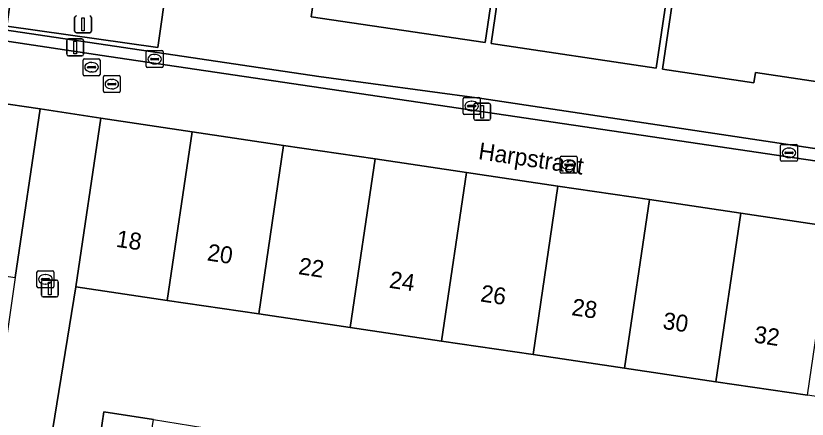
# Model space of a CAD drawing. Extents: x 164148 to 165261, y 382513 to 383432.
# Drawn here: x 164428.5 to 164475.24, y 383341.98 to 383365.77 of the extents above; entities that cross this region are included whole.
import ezdxf

# ---------------------------------------------------------------- set-up
doc = ezdxf.new("R2010")
doc.units = 0
for name, color, linetype in [('IMGEO_Brandkraan', 7, 'Continuous'), ('IMGEO_Erf', 7, 'Continuous'), ('IMGEO_Groenvoorziening', 7, 'Continuous'), ('IMGEO_Hek', 7, 'Continuous'), ('IMGEO_Kolk', 7, 'Continuous'), ('IMGEO_Lichtmast', 7, 'Continuous'), ('IMGEO_Openbare_ruimte_label', 7, 'Continuous'), ('IMGEO_Pand', 7, 'Continuous'), ('IMGEO_Pand_nummerreeks', 7, 'Continuous'), ('IMGEO_Rioolput', 7, 'Continuous'), ('IMGEO_Voetpad_open', 7, 'Continuous')]:
    doc.layers.add(name, color=color, linetype=linetype)

msp = doc.modelspace()

# ---------------------------------------------------------------- linework, layer by layer
at = {"layer": 'IMGEO_Brandkraan'}
for p, q in [((164460.657, 383356.558), (164460.657, 383357.41)), ((164460.732, 383357.484), (164461.584, 383357.484)), ((164461.658, 383357.41), (164461.658, 383356.558)), ((164460.916, 383356.978), (164460.916, 383356.99)), ((164461.354, 383356.941), (164460.956, 383356.941)), ((164460.959, 383357.027), (164461.357, 383357.027)), ((164461.145, 383357.264), (164461.17, 383357.264)), ((164461.4, 383356.99), (164461.4, 383356.978)), ((164461.584, 383356.484), (164460.732, 383356.484)), ((164461.168, 383356.704), (164461.143, 383356.704))]:
    msp.add_line(p, q, dxfattribs=at)
for points in [[(164460.657, 383356.558), (164460.657, 383357.41)], [(164460.732, 383357.484), (164461.584, 383357.484)], [(164461.658, 383357.41), (164461.658, 383356.558)], [(164461.584, 383356.484), (164460.732, 383356.484)]]:
    msp.add_lwpolyline(points, dxfattribs=at)
for centre, radius, start, end in [((164460.734, 383357.408), 0.0765, 91.552, 178.448), ((164460.734, 383357.408), 0.0765, 91.552, 178.448), ((164461.582, 383357.408), 0.0765, 1.552, 88.448), ((164461.582, 383357.408), 0.0765, 1.552, 88.448), ((164460.956, 383356.987), 0.0403, 85.8775, 175.7526), ((164460.953, 383356.977), 0.0366, 178.938, 274.7102), ((164461.357, 383356.984), 0.043, 264.8664, 352.4533), ((164461.361, 383356.989), 0.0386, 1.7309, 96.639), ((164460.734, 383356.56), 0.0765, 181.552, 268.448), ((164460.734, 383356.56), 0.0765, 181.552, 268.448), ((164461.582, 383356.56), 0.0765, 271.552, 358.448), ((164461.582, 383356.56), 0.0765, 271.552, 358.448)]:
    msp.add_arc(centre, radius, start, end, dxfattribs=at)
for centre, major_axis, ratio, start_param, end_param in [((164461.144, 383356.984), (-0.387, 0.002), 0.722429, 4.712389, 7.853982), ((164461.169, 383356.984), (-0.39, 0.002), 0.717154, 1.570796, 4.712389)]:
    msp.add_ellipse(centre, major_axis=major_axis, ratio=ratio, start_param=start_param, end_param=end_param, dxfattribs=at)
at = {"layer": 'IMGEO_Erf'}
for points in [[(164496.172, 383394.152), (164495.205, 383395.312), (164485.846, 383406.541), (164475.669, 383398.705), (164457.962, 383391.157), (164451.983, 383388.33), (164443.993, 383384.279), (164439.097, 383382.204), (164431.513, 383378.99), (164421.044, 383374.785), (164425.292, 383365.326), (164446.405, 383362.194), (164456.026, 383360.895), (164526.656, 383350.3), (164530.567, 383353.579)], [(164444.272, 383366.824), (164437.44, 383367.793), (164436.888, 383363.902), (164427.967, 383365.167), (164429.354, 383374.939), (164445.106, 383372.705)], [(164466.322, 383362.688), (164456.569, 383364.138), (164457.451, 383370.073), (164467.204, 383368.623)], [(164480.652, 383342.588), (164475.251, 383343.388), (164469.85, 383344.188), (164464.449, 383344.988), (164459.047, 383345.788), (164453.646, 383346.588), (164448.245, 383347.387), (164442.844, 383348.187), (164437.443, 383348.987), (164432.042, 383349.787), (164430.539, 383340.579), (164484.639, 383332.608), (164486.005, 383341.796)], [(164436.622, 383341.954), (164439.537, 383341.498), (164439.224, 383339.495), (164436.308, 383339.951), (164433.393, 383340.407), (164433.706, 383342.41)]]:
    msp.add_lwpolyline(points, close=True, dxfattribs=at)
for points in [[(164457.191, 383370.718), (164456.22, 383364.19), (164445.943, 383365.718), (164446.895, 383372.431)], [(164511.684, 383370.001), (164510.233, 383359.776), (164501.382, 383361.033), (164501.681, 383363.14), (164500, 383363.392), (164499.006, 383363.541), (164498.259, 383358.532), (164472.187, 383362.422), (164472.098, 383361.829), (164466.687, 383362.633), (164467.658, 383369.162)]]:
    msp.add_lwpolyline(points, dxfattribs=at)
at = {"layer": 'IMGEO_Groenvoorziening'}
msp.add_lwpolyline([(164433.986, 383363.368), (164526.587, 383349.71), (164526.656, 383350.3), (164456.026, 383360.895), (164446.405, 383362.194), (164425.292, 383365.326), (164425.46, 383364.655)], close=True, dxfattribs=at)
at = {"layer": 'IMGEO_Hek'}
msp.add_lwpolyline([(164526.656, 383350.3), (164456.026, 383360.895), (164446.405, 383362.194), (164425.292, 383365.326)], dxfattribs=at)
at = {"layer": 'IMGEO_Kolk'}
for p, q in [((164436.202, 383362.793), (164436.202, 383363.645)), ((164436.277, 383363.719), (164437.129, 383363.719)), ((164436.69, 383363.499), (164436.715, 383363.499)), ((164437.203, 383363.645), (164437.203, 383362.793)), ((164436.461, 383363.213), (164436.461, 383363.225)), ((164436.899, 383363.176), (164436.501, 383363.176)), ((164436.504, 383363.262), (164436.902, 383363.262)), ((164436.945, 383363.225), (164436.945, 383363.213)), ((164437.129, 383362.719), (164436.277, 383362.719)), ((164436.713, 383362.939), (164436.688, 383362.939)), ((164454.921, 383360.025), (164454.921, 383360.877)), ((164454.996, 383360.951), (164455.848, 383360.951)), ((164455.409, 383360.731), (164455.434, 383360.731)), ((164455.922, 383360.877), (164455.922, 383360.025)), ((164455.18, 383360.445), (164455.18, 383360.457)), ((164455.618, 383360.408), (164455.22, 383360.408)), ((164455.223, 383360.494), (164455.621, 383360.494)), ((164455.664, 383360.457), (164455.664, 383360.445)), ((164455.848, 383359.951), (164454.996, 383359.951)), ((164455.432, 383360.171), (164455.407, 383360.171)), ((164473.664, 383357.264), (164473.664, 383358.116)), ((164473.739, 383358.19), (164474.591, 383358.19)), ((164474.152, 383357.97), (164474.177, 383357.97)), ((164474.665, 383358.116), (164474.665, 383357.264)), ((164473.923, 383357.684), (164473.923, 383357.696)), ((164474.361, 383357.647), (164473.963, 383357.647)), ((164473.966, 383357.733), (164474.364, 383357.733)), ((164474.175, 383357.41), (164474.15, 383357.41)), ((164474.407, 383357.696), (164474.407, 383357.684)), ((164474.591, 383357.19), (164473.739, 383357.19)), ((164429.748, 383349.803), (164429.748, 383350.655)), ((164429.823, 383350.729), (164430.675, 383350.729)), ((164430.236, 383350.509), (164430.261, 383350.509)), ((164430.749, 383350.655), (164430.749, 383349.803)), ((164430.007, 383350.223), (164430.007, 383350.235)), ((164430.445, 383350.186), (164430.047, 383350.186)), ((164430.05, 383350.272), (164430.448, 383350.272)), ((164430.259, 383349.949), (164430.234, 383349.949)), ((164430.491, 383350.235), (164430.491, 383350.223)), ((164430.675, 383349.729), (164429.823, 383349.729))]:
    msp.add_line(p, q, dxfattribs=at)
for points in [[(164436.202, 383362.793), (164436.202, 383363.645)], [(164436.277, 383363.719), (164437.129, 383363.719)], [(164437.203, 383363.645), (164437.203, 383362.793)], [(164437.129, 383362.719), (164436.277, 383362.719)], [(164454.921, 383360.025), (164454.921, 383360.877)], [(164454.996, 383360.951), (164455.848, 383360.951)], [(164455.922, 383360.877), (164455.922, 383360.025)], [(164455.848, 383359.951), (164454.996, 383359.951)], [(164473.664, 383357.264), (164473.664, 383358.116)], [(164473.739, 383358.19), (164474.591, 383358.19)], [(164474.665, 383358.116), (164474.665, 383357.264)], [(164474.591, 383357.19), (164473.739, 383357.19)], [(164429.748, 383349.803), (164429.748, 383350.655)], [(164429.823, 383350.729), (164430.675, 383350.729)], [(164430.749, 383350.655), (164430.749, 383349.803)], [(164430.675, 383349.729), (164429.823, 383349.729)]]:
    msp.add_lwpolyline(points, dxfattribs=at)
for centre, radius, start, end in [((164436.279, 383363.643), 0.0765, 91.552, 178.448), ((164436.279, 383363.643), 0.0765, 91.552, 178.448), ((164437.127, 383363.643), 0.0765, 1.552, 88.448), ((164437.127, 383363.643), 0.0765, 1.552, 88.448), ((164436.501, 383363.222), 0.0403, 85.8775, 175.7526), ((164436.498, 383363.212), 0.0366, 178.938, 274.7102), ((164436.902, 383363.219), 0.043, 264.8664, 352.4533), ((164436.906, 383363.224), 0.0386, 1.7309, 96.639), ((164436.279, 383362.795), 0.0765, 181.552, 268.448), ((164436.279, 383362.795), 0.0765, 181.552, 268.448), ((164437.127, 383362.795), 0.0765, 271.552, 358.448), ((164437.127, 383362.795), 0.0765, 271.552, 358.448), ((164454.998, 383360.875), 0.0765, 91.552, 178.448), ((164454.998, 383360.875), 0.0765, 91.552, 178.448), ((164455.846, 383360.875), 0.0765, 1.552, 88.448), ((164455.846, 383360.875), 0.0765, 1.552, 88.448), ((164455.22, 383360.454), 0.0403, 85.8775, 175.7526), ((164455.217, 383360.444), 0.0366, 178.938, 274.7102), ((164455.621, 383360.451), 0.043, 264.8664, 352.4533), ((164455.625, 383360.456), 0.0386, 1.7309, 96.639), ((164454.998, 383360.027), 0.0765, 181.552, 268.448), ((164454.998, 383360.027), 0.0765, 181.552, 268.448), ((164455.846, 383360.027), 0.0765, 271.552, 358.448), ((164455.846, 383360.027), 0.0765, 271.552, 358.448), ((164473.741, 383358.114), 0.0765, 91.552, 178.448), ((164473.741, 383358.114), 0.0765, 91.552, 178.448), ((164474.589, 383358.114), 0.0765, 1.552, 88.448), ((164474.589, 383358.114), 0.0765, 1.552, 88.448), ((164473.963, 383357.693), 0.0403, 85.8775, 175.7526), ((164473.96, 383357.683), 0.0366, 178.938, 274.7102), ((164474.364, 383357.69), 0.043, 264.8664, 352.4533), ((164474.368, 383357.695), 0.0386, 1.7309, 96.639), ((164473.741, 383357.266), 0.0765, 181.552, 268.448), ((164473.741, 383357.266), 0.0765, 181.552, 268.448), ((164474.589, 383357.266), 0.0765, 271.552, 358.448), ((164474.589, 383357.266), 0.0765, 271.552, 358.448), ((164429.825, 383350.653), 0.0765, 91.552, 178.448), ((164429.825, 383350.653), 0.0765, 91.552, 178.448), ((164430.673, 383350.653), 0.0765, 1.552, 88.448), ((164430.673, 383350.653), 0.0765, 1.552, 88.448), ((164430.047, 383350.232), 0.0403, 85.8775, 175.7526), ((164430.044, 383350.222), 0.0366, 178.938, 274.7102), ((164430.448, 383350.229), 0.043, 264.8664, 352.4533), ((164430.452, 383350.234), 0.0386, 1.7309, 96.639), ((164429.825, 383349.805), 0.0765, 181.552, 268.448), ((164429.825, 383349.805), 0.0765, 181.552, 268.448), ((164430.673, 383349.805), 0.0765, 271.552, 358.448), ((164430.673, 383349.805), 0.0765, 271.552, 358.448)]:
    msp.add_arc(centre, radius, start, end, dxfattribs=at)
for centre, major_axis, ratio, start_param, end_param in [((164436.689, 383363.219), (-0.387, 0.002), 0.722429, 4.712389, 7.853982), ((164436.714, 383363.219), (-0.39, 0.002), 0.717154, 1.570796, 4.712389), ((164455.408, 383360.451), (-0.387, 0.002), 0.722429, 4.712389, 7.853982), ((164455.433, 383360.451), (-0.39, 0.002), 0.717154, 1.570796, 4.712389), ((164474.151, 383357.69), (-0.387, 0.002), 0.722429, 4.712389, 7.853982), ((164474.176, 383357.69), (-0.39, 0.002), 0.717154, 1.570796, 4.712389), ((164430.235, 383350.229), (-0.387, 0.002), 0.722429, 4.712389, 7.853982), ((164430.26, 383350.229), (-0.39, 0.002), 0.717154, 1.570796, 4.712389)]:
    msp.add_ellipse(centre, major_axis=major_axis, ratio=ratio, start_param=start_param, end_param=end_param, dxfattribs=at)
at = {"layer": 'IMGEO_Lichtmast'}
for p, q in [((164431.975, 383364.871), (164431.975, 383365.671)), ((164431.975, 383365.671), (164431.975, 383364.871)), ((164432.965, 383365.671), (164432.965, 383364.871)), ((164432.965, 383364.871), (164432.965, 383365.671)), ((164431.608, 383364.411), (164432.398, 383364.411)), ((164432.398, 383364.411), (164431.608, 383364.411)), ((164432.865, 383364.771), (164432.075, 383364.771)), ((164432.075, 383364.771), (164432.865, 383364.771)), ((164431.508, 383363.511), (164431.508, 383364.311)), ((164431.508, 383364.311), (164431.508, 383363.511)), ((164432.498, 383364.311), (164432.498, 383363.511)), ((164432.498, 383363.511), (164432.498, 383364.311)), ((164432.398, 383363.411), (164431.608, 383363.411)), ((164431.608, 383363.411), (164432.398, 383363.411)), ((164455.551, 383359.715), (164455.551, 383360.515)), ((164455.551, 383360.515), (164455.551, 383359.715)), ((164455.651, 383360.615), (164456.441, 383360.615)), ((164456.441, 383360.615), (164455.651, 383360.615)), ((164456.541, 383360.515), (164456.541, 383359.715)), ((164456.541, 383359.715), (164456.541, 383360.515)), ((164456.441, 383359.615), (164455.651, 383359.615)), ((164455.651, 383359.615), (164456.441, 383359.615)), ((164430.013, 383349.287), (164430.013, 383350.087)), ((164430.013, 383350.087), (164430.013, 383349.287)), ((164430.113, 383350.187), (164430.903, 383350.187)), ((164430.903, 383350.187), (164430.113, 383350.187)), ((164431.003, 383350.087), (164431.003, 383349.287)), ((164431.003, 383349.287), (164431.003, 383350.087)), ((164430.903, 383349.187), (164430.113, 383349.187)), ((164430.113, 383349.187), (164430.903, 383349.187))]:
    msp.add_line(p, q, dxfattribs=at)
for points in [[(164432.395, 383365.646), (164432.545, 383365.646), (164432.545, 383364.896), (164432.395, 383364.896), (164432.395, 383365.646)], [(164431.928, 383364.286), (164432.078, 383364.286), (164432.078, 383363.536), (164431.928, 383363.536), (164431.928, 383364.286)], [(164455.971, 383360.49), (164456.121, 383360.49), (164456.121, 383359.74), (164455.971, 383359.74), (164455.971, 383360.49)], [(164430.433, 383350.062), (164430.583, 383350.062), (164430.583, 383349.312), (164430.433, 383349.312), (164430.433, 383350.062)]]:
    msp.add_lwpolyline(points, dxfattribs=at)
for centre, start, end in [((164432.075, 383365.671), 90, 180), ((164432.075, 383365.671), 90, 180), ((164432.865, 383365.671), 0, 90), ((164432.865, 383365.671), 360, 90), ((164432.075, 383364.871), 180, 270), ((164432.075, 383364.871), 180, 270), ((164432.865, 383364.871), 270, 0), ((164432.865, 383364.871), 270, 0), ((164431.608, 383364.311), 90, 180), ((164431.608, 383364.311), 90, 180), ((164432.398, 383364.311), 0, 90), ((164432.398, 383364.311), 360, 90), ((164431.608, 383363.511), 180, 270), ((164431.608, 383363.511), 180, 270), ((164432.398, 383363.511), 270, 0), ((164432.398, 383363.511), 270, 0), ((164455.651, 383360.515), 90, 180), ((164455.651, 383360.515), 90, 180), ((164456.441, 383360.515), 0, 90), ((164456.441, 383360.515), 360, 90), ((164455.651, 383359.715), 180, 270), ((164455.651, 383359.715), 180, 270), ((164456.441, 383359.715), 270, 0), ((164456.441, 383359.715), 270, 0), ((164430.113, 383350.087), 90, 180), ((164430.113, 383350.087), 90, 180), ((164430.903, 383350.087), 0, 90), ((164430.903, 383350.087), 360, 90), ((164430.113, 383349.287), 180, 270), ((164430.113, 383349.287), 180, 270), ((164430.903, 383349.287), 270, 0), ((164430.903, 383349.287), 270, 0)]:
    msp.add_arc(centre, 0.1, start, end, dxfattribs=at)
at = {"layer": 'IMGEO_Pand'}
for points in [[(164436.888, 383363.902), (164437.44, 383367.793), (164444.272, 383366.824), (164445.106, 383372.705), (164429.354, 383374.939), (164427.967, 383365.167)], [(164466.322, 383362.688), (164467.204, 383368.623), (164457.451, 383370.073), (164456.569, 383364.138)], [(164423.065, 383351.135), (164428.467, 383350.338), (164429.933, 383360.28), (164424.531, 383361.077)], [(164437.443, 383348.987), (164438.915, 383358.929), (164433.514, 383359.729), (164432.042, 383349.787)], [(164444.316, 383358.129), (164438.915, 383358.929), (164437.443, 383348.987), (164442.844, 383348.187)], [(164444.316, 383358.129), (164442.844, 383348.187), (164448.245, 383347.387), (164449.718, 383357.329)], [(164448.245, 383347.387), (164453.646, 383346.588), (164455.119, 383356.529), (164449.718, 383357.329)], [(164455.119, 383356.529), (164453.646, 383346.588), (164459.047, 383345.788), (164460.52, 383355.729)], [(164464.449, 383344.988), (164465.921, 383354.929), (164460.52, 383355.729), (164459.047, 383345.788)], [(164471.322, 383354.13), (164465.921, 383354.929), (164464.449, 383344.988), (164469.85, 383344.188)], [(164475.251, 383343.388), (164476.723, 383353.33), (164471.322, 383354.13), (164469.85, 383344.188)], [(164436.622, 383341.954), (164433.706, 383342.41), (164433.393, 383340.407), (164436.308, 383339.951)]]:
    msp.add_lwpolyline(points, close=True, dxfattribs=at)
for points in [[(164446.895, 383372.431), (164445.943, 383365.718), (164456.22, 383364.19), (164457.191, 383370.718)], [(164467.658, 383369.162), (164466.687, 383362.633), (164472.098, 383361.829), (164472.187, 383362.422), (164498.259, 383358.532), (164499.006, 383363.541), (164500, 383363.392), (164501.681, 383363.14), (164501.382, 383361.033), (164510.233, 383359.776), (164511.684, 383370.001)]]:
    msp.add_lwpolyline(points, dxfattribs=at)
at = {"layer": 'IMGEO_Rioolput'}
for p, q in [((164432.472, 383362.313), (164432.472, 383363.165)), ((164432.547, 383363.239), (164433.399, 383363.239)), ((164432.96, 383363.019), (164432.985, 383363.019)), ((164433.473, 383363.165), (164433.473, 383362.313)), ((164432.731, 383362.733), (164432.731, 383362.745)), ((164433.169, 383362.696), (164432.771, 383362.696)), ((164432.774, 383362.782), (164433.172, 383362.782)), ((164433.215, 383362.745), (164433.215, 383362.733)), ((164433.399, 383362.239), (164432.547, 383362.239)), ((164432.983, 383362.459), (164432.958, 383362.459)), ((164433.671, 383361.319), (164433.671, 383362.171)), ((164433.746, 383362.245), (164434.598, 383362.245)), ((164434.672, 383362.171), (164434.672, 383361.319)), ((164433.93, 383361.739), (164433.93, 383361.751)), ((164434.368, 383361.702), (164433.97, 383361.702)), ((164433.973, 383361.788), (164434.371, 383361.788)), ((164434.159, 383362.025), (164434.184, 383362.025)), ((164434.414, 383361.751), (164434.414, 383361.739)), ((164434.598, 383361.245), (164433.746, 383361.245)), ((164434.182, 383361.465), (164434.157, 383361.465))]:
    msp.add_line(p, q, dxfattribs=at)
for points in [[(164432.472, 383362.313), (164432.472, 383363.165)], [(164432.547, 383363.239), (164433.399, 383363.239)], [(164433.473, 383363.165), (164433.473, 383362.313)], [(164433.399, 383362.239), (164432.547, 383362.239)], [(164433.671, 383361.319), (164433.671, 383362.171)], [(164433.746, 383362.245), (164434.598, 383362.245)], [(164434.672, 383362.171), (164434.672, 383361.319)], [(164434.598, 383361.245), (164433.746, 383361.245)]]:
    msp.add_lwpolyline(points, dxfattribs=at)
for centre, radius, start, end in [((164432.549, 383363.163), 0.0765, 91.552, 178.448), ((164432.549, 383363.163), 0.0765, 91.552, 178.448), ((164433.397, 383363.163), 0.0765, 1.552, 88.448), ((164433.397, 383363.163), 0.0765, 1.552, 88.448), ((164432.771, 383362.742), 0.0403, 85.8775, 175.7526), ((164432.768, 383362.732), 0.0366, 178.938, 274.7102), ((164433.172, 383362.739), 0.043, 264.8664, 352.4533), ((164433.176, 383362.744), 0.0386, 1.7309, 96.639), ((164432.549, 383362.315), 0.0765, 181.552, 268.448), ((164432.549, 383362.315), 0.0765, 181.552, 268.448), ((164433.397, 383362.315), 0.0765, 271.552, 358.448), ((164433.397, 383362.315), 0.0765, 271.552, 358.448), ((164433.748, 383362.169), 0.0765, 91.552, 178.448), ((164433.748, 383362.169), 0.0765, 91.552, 178.448), ((164434.596, 383362.169), 0.0765, 1.552, 88.448), ((164434.596, 383362.169), 0.0765, 1.552, 88.448), ((164433.97, 383361.748), 0.0403, 85.8775, 175.7526), ((164433.967, 383361.738), 0.0366, 178.938, 274.7102), ((164434.371, 383361.745), 0.043, 264.8664, 352.4533), ((164434.375, 383361.75), 0.0386, 1.7309, 96.639), ((164433.748, 383361.321), 0.0765, 181.552, 268.448), ((164433.748, 383361.321), 0.0765, 181.552, 268.448), ((164434.596, 383361.321), 0.0765, 271.552, 358.448), ((164434.596, 383361.321), 0.0765, 271.552, 358.448)]:
    msp.add_arc(centre, radius, start, end, dxfattribs=at)
for centre, major_axis, ratio, start_param, end_param in [((164432.959, 383362.739), (-0.387, 0.002), 0.722429, 4.712389, 7.853982), ((164432.984, 383362.739), (-0.39, 0.002), 0.717154, 1.570796, 4.712389), ((164434.158, 383361.745), (-0.387, 0.002), 0.722429, 4.712389, 7.853982), ((164434.183, 383361.745), (-0.39, 0.002), 0.717154, 1.570796, 4.712389)]:
    msp.add_ellipse(centre, major_axis=major_axis, ratio=ratio, start_param=start_param, end_param=end_param, dxfattribs=at)
at = {"layer": 'IMGEO_Voetpad_open'}
for points in [[(164392.122, 383365.858), (164397.524, 383365.061), (164402.925, 383364.265), (164408.327, 383363.468), (164413.728, 383362.671), (164419.13, 383361.874), (164424.531, 383361.077), (164429.933, 383360.28), (164433.514, 383359.729), (164438.915, 383358.929), (164444.316, 383358.129), (164449.718, 383357.329), (164455.119, 383356.529), (164460.52, 383355.729), (164465.921, 383354.929), (164471.322, 383354.13), (164476.723, 383353.33)], [(164433.986, 383363.368), (164425.46, 383364.655), (164422.515, 383365.1), (164419.068, 383365.739)], [(164526.587, 383349.71), (164433.986, 383363.368)], [(164536.279, 383342.366), (164534.257, 383344.81), (164533.932, 383342.614), (164532.785, 383334.868), (164531.533, 383325.667), (164488.094, 383332.078), (164489.556, 383341.27), (164491.029, 383351.211), (164487.477, 383351.737), (164486.005, 383341.796), (164484.639, 383332.608), (164430.539, 383340.579), (164432.042, 383349.787), (164433.514, 383359.729), (164429.933, 383360.28), (164428.467, 383350.338), (164427.117, 383341.092), (164383.799, 383347.483), (164383.752, 383345.842), (164388.671, 383345.12), (164390.731, 383344.808), (164424.372, 383339.822)]]:
    msp.add_lwpolyline(points, dxfattribs=at)

# ---------------------------------------------------------------- texts
at = {"layer": 'IMGEO_Openbare_ruimte_label'}
msp.add_text('Harpstraat', height=1, rotation=351.5457, dxfattribs=at).set_placement((164455.777, 383357.323))
at = {"layer": 'IMGEO_Pand_nummerreeks'}
for s, p in [('18', (164434.379, 383352.154)), ('20', (164439.759, 383351.348)), ('22', (164445.15, 383350.54)), ('24', (164450.513, 383349.737)), ('26', (164455.901, 383348.93)), ('28', (164461.284, 383348.123)), ('30', (164466.664, 383347.317)), ('32', (164472.055, 383346.51))]:
    msp.add_text(s, height=1, rotation=351.4801, dxfattribs=at).set_placement(p)

doc.saveas('drawing.dxf')
